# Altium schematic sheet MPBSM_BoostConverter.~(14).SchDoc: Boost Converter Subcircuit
size A3; Date: Not shown in title block; ApprovedBy: Not shown in title block; CheckedBy: Not shown in title block; Author: Not shown in title block; CompanyName: Not shown in title block; DrawnBy: Not shown in title block; Engineer: Not shown in title block; Organization: Not shown in title block; Address1: Not shown in title block; Address2: Not shown in title block; Address3: Not shown in title block; Address4: Not shown in title block; DocumentNumber: 4; Revision: Use project parameter SCH_Rev; SheetNumber: 4; SheetTotal: 12; PageSetup: Record=PageOptions¦CenterHorizontal=True¦CenterVertical=True¦PrintScale=0.69¦XCorrection=1.00¦YCorrection=1.00¦PrintKind=0¦BorderSize=5000000¦LeftOffset=0¦BottomOffset=0¦Orientation=2¦PaperLength=1000¦PaperWidth=1000¦Scale=100¦PaperSource=15¦PrintQuality=600¦MediaType=1¦DitherType=10¦PaperKind=Letter¦PrintScaleMode=1
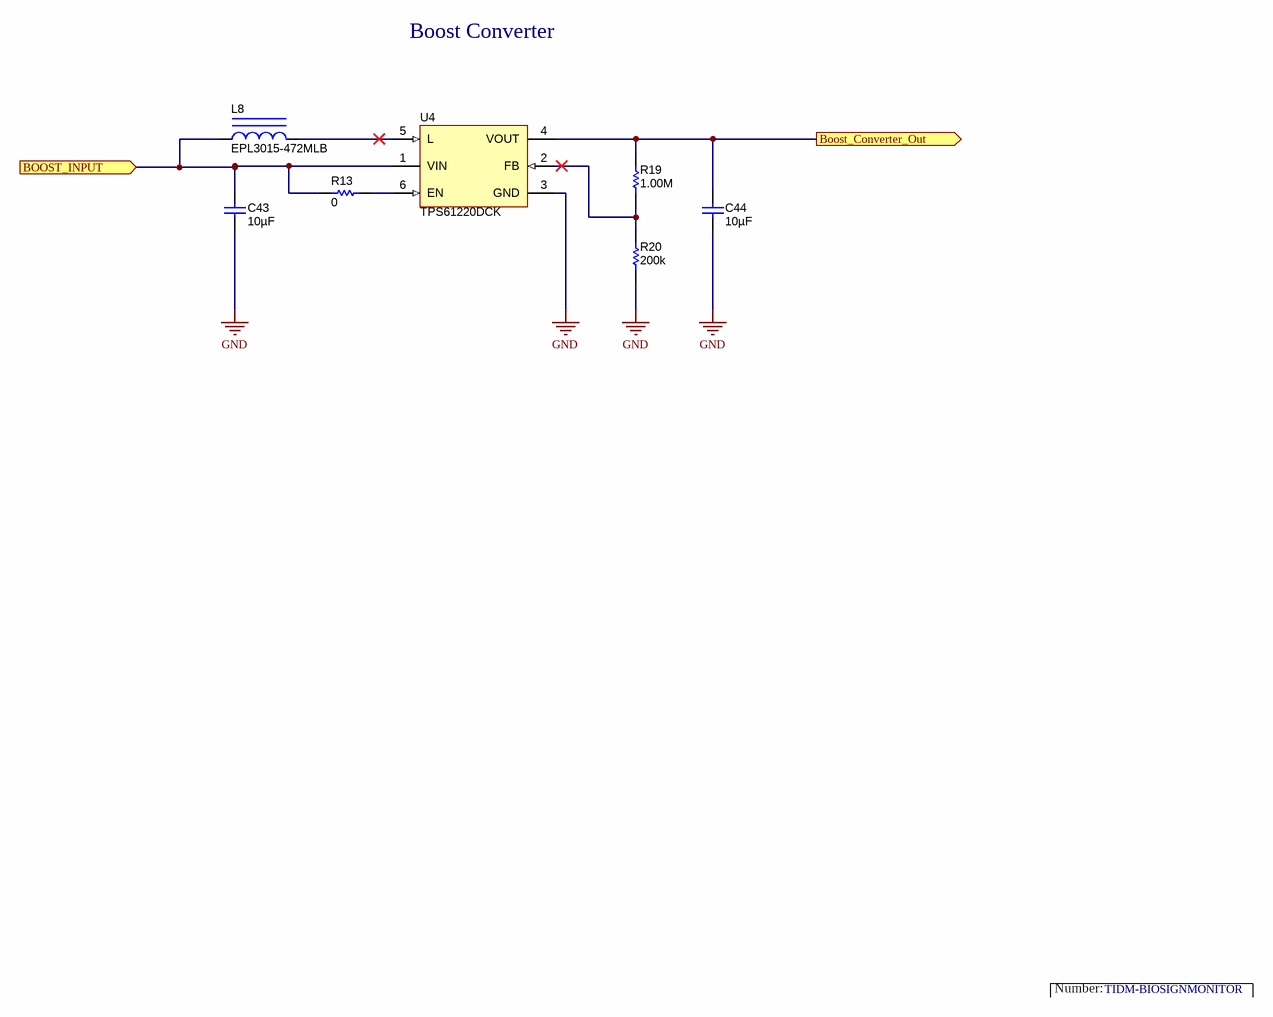
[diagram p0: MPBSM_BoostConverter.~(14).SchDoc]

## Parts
C43  ValueDisplayed: 10µF  [0402]  (hidden comment: CL05A106MQ5NUNC)
C44  ValueDisplayed: 10µF  [0402]  (hidden comment: CL05A106MQ5NUNC)
L8  EPL3015-472MLB  [EPL3015]
R13  ValueDisplayed: 0  [0402]  (hidden comment: ERJ-2GE0R00X)
R19  ValueDisplayed: 1.00M  [0402]  (hidden comment: ERJ-2RKF1004X)
R20  ValueDisplayed: 200k  [0402]  (hidden comment: ERJ-2RKF2003X)
U4  TPS61220DCK  [DCK0006A_N]

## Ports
Boost_Converter_Out (out), BOOST_INPUT (in)

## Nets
GND: C43.2 C44.2 R20.1 U4.3(GND)
Boost_Converter_Out: C44.1 R19.2 U4.4(VOUT) ; port Boost_Converter_Out
BOOST_INPUT: C43.1 L8.1 R13.1 U4.1(VIN) ; port BOOST_INPUT
NetL8_2: L8.2 U4.5(L)
NetR13_2: R13.2 U4.6(EN)
NetR19_1: R19.1 R20.2 U4.2(FB)

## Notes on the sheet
- Boost Converter
- Number:
- TIDM-BIOSIGNMONITOR

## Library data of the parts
C43 C44 = CL05A106MQ5NUNC: CAP, CERM, 10 µF, 6.3 V, +/- 20%, X5R, 0402; Manufacturer: Samsung; Polarized: N; CompType: Capacitor; Value: 10uF; U/M: EA; Cap_F: 0.00001; Tolerance_%: 20; Value1: Unknown; VDC_V: 6.3; Value2: 6.3V; TaMin_C: -55; TaMax_C: 85
L8 = EPL3015-472MLB: Inductor, Shielded, Ferrite, 4.7uH, 1.2A, 0.14 ohm, SMD; Manufacturer: Coilcraft; Ind_H: 4.7E-6; ValueDisplayed: 4.7µH; Imax_A: 1.2; Irms: 1.4A @ 40C rise; Isat: 1.2A @ 30% inductance drop; DCR_ohm: 0.14
R13 = ERJ-2GE0R00X: RES, 0, 5%, 0.063 W, 0402; Manufacturer: Panasonic; CompType: Resistor; Value: 0; Value_Code: 0000; Tolerance_%: 5; Power_W: 0.063; Value2: 0.063W; VDC_V: 50; TempCo: 600 ppm/C; EIA_Code: E24; U/M: EA
R19 = ERJ-2RKF1004X: RES, 1.00 M, 1%, 0.1 W, 0402; Manufacturer: Panasonic; CompType: Resistor; Value: 1.00Meg; Res_ohm: 1000000; Value_Code: 1M00; Tolerance_%: 1; Power_W: 0.1; Value2: 0.1W; VDC_V: 50; TempCo: 100 ppm/C; EIA_Code: E96; U/M: EA
R20 = ERJ-2RKF2003X: RES, 200 k, 1%, 0.1 W, 0402; Manufacturer: Panasonic; CompType: Resistor; Value: 200k; Res_ohm: 200000; Tolerance_%: 1; Power_W: 0.1; Value2: 0.1W; VDC_V: 50; TempCo: 100 ppm/C; EIA_Code: E96; U/M: EA
U4 = TPS61220DCK: LOW INPUT VOLTAGE STEP-UP CONVERTER IN 6 PIN SC-70 PACKAGE, DCK0006A; Manufacturer: Texas Instruments; SymbolCreator: a0799628; CompType: IC; U/M: EA; Value: Analog; Value1: 0.7 V to 5.5 V; Value2: 200 mA; TaMax_C: -40°C; TaMin_C: 125°C; InputVoltageMin_V: 0.7 V; InputVoltageMax_V: 5.5 V; SwitchingFrequency: 2 MHz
